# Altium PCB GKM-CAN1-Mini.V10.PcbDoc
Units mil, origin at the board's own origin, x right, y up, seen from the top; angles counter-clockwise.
Board outline 725.03 x 557.03 mil, 2 copper layers (Top Layer, Bottom Layer); 2 components, 22 nets, 10 pads, 0 vias.
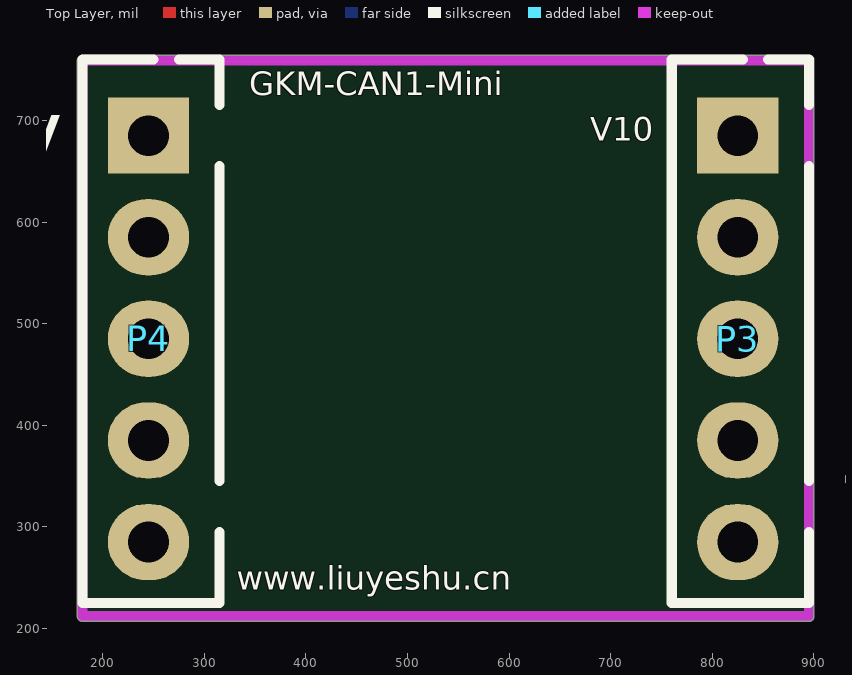
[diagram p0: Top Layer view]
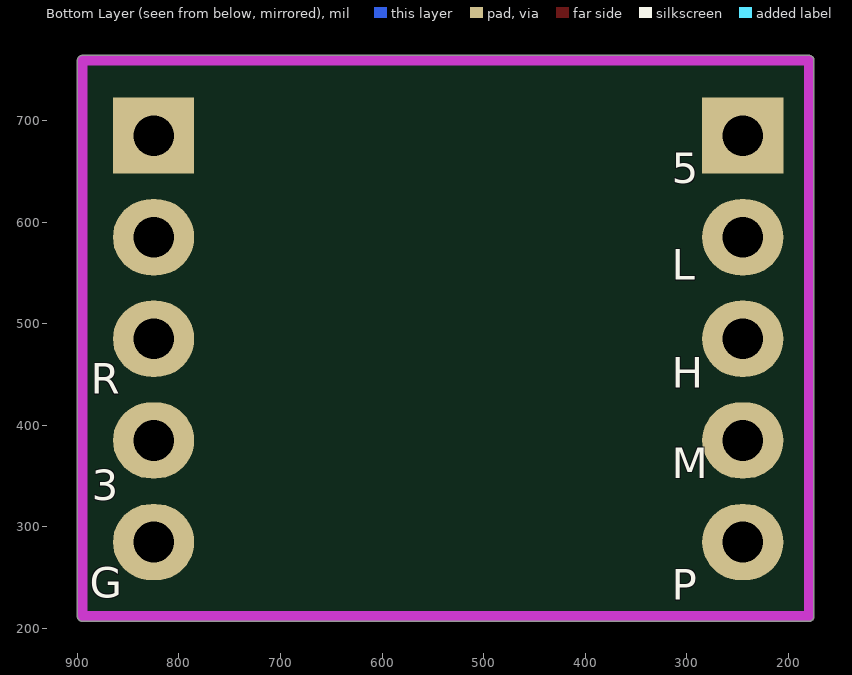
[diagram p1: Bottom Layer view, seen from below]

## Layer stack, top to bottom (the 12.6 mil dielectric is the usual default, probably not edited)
Top Layer: signal copper 1.4
Dielectric: dielectric 12.6, FR-4, Dk 4.8
Bottom Layer: signal copper 1.4

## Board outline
174.98,212 ccw(c180,212) 180,206.99 895,206.99 ccw(c895,212) 900.02,212 900.02,759 ccw(c895,759) 895,764.02 181,764.02 ccw(c181,759) 180.5,763.99 ccw(c180,759) 174.98,759

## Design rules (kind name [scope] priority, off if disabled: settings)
Clearance [All] p1: gap=5
PolygonConnect [All] p1: connectstyle=Relief reliefconductorwidth=10 reliefentries=4 polygonreliefangle="90 Angle"
RoutingVias [All] p1: holewidth=28 width=50 viastyle="Through Hole" minholewidth=28 minwidth=50 maxholewidth=28 maxwidth=50
SilkscreenOverComponentPads [All] p1: minsilkscreentomaskgap=10
SolderMaskExpansion [All] p1: expansion=4
Width [All] p1: maxlimit=100 minlimit=5 preferedwidth=10
27 further rules are at their usual default settings.

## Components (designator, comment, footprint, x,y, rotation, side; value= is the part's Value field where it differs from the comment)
P3 "Header5" "MY PIN5" 825,685 r270 top
P4 "Header5" "MY PIN5" 245,685 r270 top

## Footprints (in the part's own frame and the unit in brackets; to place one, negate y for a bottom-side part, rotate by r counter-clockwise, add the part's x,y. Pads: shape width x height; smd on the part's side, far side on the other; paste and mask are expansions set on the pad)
"MY PIN5" [mil]
  rect 75x80 hole 40: 1(0,0)
  oval 75x80 hole 40: 2(100,0) 3(200,0) 4(300,0) 5(400,0)
  silkscreen extent -75,-65 460,70

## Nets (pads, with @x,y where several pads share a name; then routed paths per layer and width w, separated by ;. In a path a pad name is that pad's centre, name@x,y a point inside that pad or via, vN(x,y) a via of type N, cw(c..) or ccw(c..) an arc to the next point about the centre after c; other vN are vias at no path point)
+3.3V: P3.4
+5V: P4.1
CAN1_H: P4.3
CAN1_L: P4.2
CAN1_RXD: 
CAN1_TXD: 
GND: P3.5
JLINK-SWCLK: P3.2
JLINK-SWDIO: P3.1
LED-CAN1: 
LED-CAN2: 
LED-FUN: 
LED-PWR: 
NetC1_1: 
NetC2_1: 
NetR7_1: 
NetR18_2: 
NRST: P3.3
USART-RX: 
USART-TX: 
USBDM: P4.4
USBDP: P4.5

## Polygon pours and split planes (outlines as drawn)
GND on Top Layer "Top Layer-No Net" (hatched 45Degree grid 20 track 10, remove dead copper, pour order 1000): 182,759 183,758 898,758

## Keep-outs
Keep-Out Layer:
  lines w10: 180,759 180,212 895,212 895,759 181,759

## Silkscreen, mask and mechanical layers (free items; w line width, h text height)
Top Overlay:
  text "GKM-CAN1-Mini" at 344,717 h40
  text "V10" at 680,672 h40
  text "5V" at 50,645 h60
  text "CAN-L" at -112,543 h60
  text "RST" at 924,450 h60
  text "CAN-H" at -119,446 h60
  text "USB-DM" at -181,342 h60
  text "3.3V" at 925,341 h60
  text "GND" at 930,232 h60
  text "www.liuyeshu.cn" at 332,230 h40
  text "USB-DP" at -184,227 h60
Bottom Overlay:
  text "5" at 315,638 h30
  text "L" at 315,543 h30
  text "H" at 315,437 h30
  text "R" at 887,431 h30
  text "M" at 315,348 h30
  text "3" at 886,326 h30
  text "G" at 888,230 h30
  text "P" at 315,228 h30

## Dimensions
245,285 to 825,285 on Top Overlay
825,585 to 825,485 on Top Overlay
180,760 to 174.98,212 on Top Overlay
180,760 to 895,760 on Top Overlay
